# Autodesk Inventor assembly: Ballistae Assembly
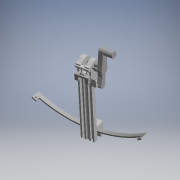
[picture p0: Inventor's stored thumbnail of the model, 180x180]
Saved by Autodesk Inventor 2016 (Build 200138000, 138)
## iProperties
Created: 2013-11
Part Number: Ballistae Assembly
Document SubType Name: Assembly
Designer: 603839
Author: 603839
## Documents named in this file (10)
- I:\ME 514\Crossbow\Ballistae_Assembly.iam
- I:\ME 514\Crossbow\String_Pulley_V2.ipt
- I:\ME 514\Crossbow\Pull_Shoe.ipt
- U:\Dominic Cupo Design Studio\Tabletop Ballistae\String holder.ipt
- I:\ME 514\Crossbow\Rachet_Prawl.ipt
- U:\Dominic Cupo Design Studio\Tabletop Ballistae\Bow Arms.ipt
- I:\ME 514\Crossbow\Main_Body+-+body+1.ipt
- I:\ME 514\Crossbow\Ratchet&Cranked_2.iam.ipt
- I:\ME 514\Crossbow\Bow.ipt
- Ratchet&Cranked_2.iam
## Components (9 placed, 8 different names)
1. String_Pulley_V2:1 — Mate:8, Mate:9
2. Pull_Shoe:1 — Mate:5, Mate:6
3. String holder:1
4. Bow Arms:1
5. Bow Arms:2
6. Rachet_Prawl:2 — Mate:1, Mate:2
7. Main_Body+-+body+1:1 — Mate:1, Mate:2, Mate:3, Mate:4, Mate:5, Mate:6, Mate:8, Mate:9, Mate:21, Mate:22, Mate:23
8. Ratchet&Cranked_2.iam:1 — Mate:3, Mate:4
9. Bow:1 — Mate:21, Mate:22, Mate:23
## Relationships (11: Mate 11)
- Mate:1: Rachet_Prawl:2 ↔ Main_Body+-+body+1:1
- Mate:2: Rachet_Prawl:2 ↔ Main_Body+-+body+1:1
- Mate:3: Main_Body+-+body+1:1 ↔ Ratchet&Cranked_2.iam:1
- Mate:4: Main_Body+-+body+1:1 ↔ Ratchet&Cranked_2.iam:1
- Mate:5: Pull_Shoe:1 ↔ Main_Body+-+body+1:1
- Mate:6: Pull_Shoe:1 ↔ Main_Body+-+body+1:1
- Mate:8: String_Pulley_V2:1 ↔ Main_Body+-+body+1:1
- Mate:9: String_Pulley_V2:1 ↔ Main_Body+-+body+1:1
- Mate:21: Main_Body+-+body+1:1 ↔ Bow:1
- Mate:22: Main_Body+-+body+1:1 ↔ Bow:1
- Mate:23: Main_Body+-+body+1:1 ↔ Bow:1
